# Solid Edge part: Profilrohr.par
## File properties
Dokumentum tartalom típus: 0
Last saved by: ahadarics
Revision: 76
Sűrűség: 0,000 kg/m^3
Pontosság: 0,990
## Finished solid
Body 1: solid body, 95 faces, 278 edges, 184 vertices.
  Faces by surface: plane 48, cylinder 47
  Edges by curve: line 184, circle 94
Bounding box of the edges (mm): 65.500 x 65.500 x 21.000, from (-32.75, -32.75, 0) to (32.75, 32.75, 21).
Cylindrical faces by radius (mm): R0.15 x20, R0.25 x20, R6.5 x2, R8 x4, R25 x1
Planar faces by outward normal: +x 11, +y 12, +z 1, -x 11, -y 12, -z 1
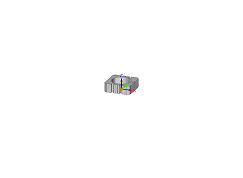
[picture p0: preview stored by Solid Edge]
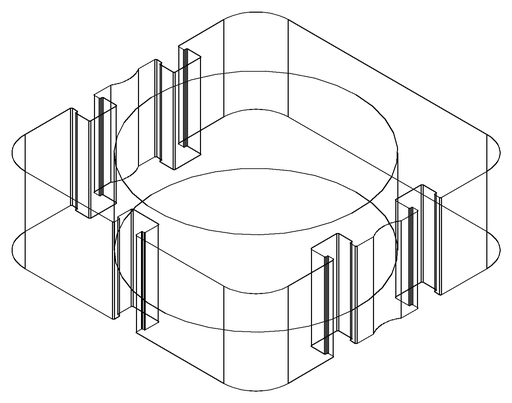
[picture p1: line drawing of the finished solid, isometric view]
